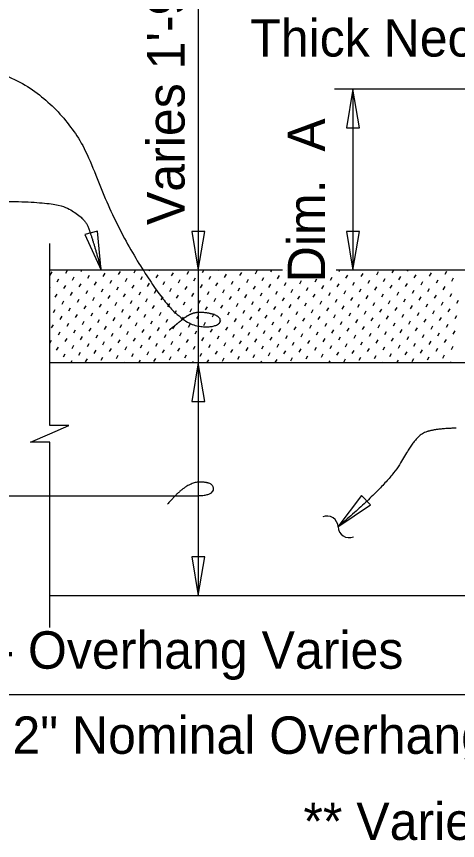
# Model space of a CAD drawing. Extents: x 21516.9 to 21586.2, y 56156.7 to 56193.6.
# Drawn here: x 21540.697 to 21543.073, y 56180.189 to 56184.631 of the extents above; entities that cross this region are included whole.
import ezdxf

# ---------------------------------------------------------------- set-up
doc = ezdxf.new("R2010")
doc.units = 0
for name, color, linetype in [('AdhocPoint_dp', 7, 'Continuous'), ('Patterning', 7, 'Continuous'), ('PlotBorder_dp', 7, 'Continuous'), ('SheetBorder_dp', 7, 'Continuous')]:
    doc.layers.add(name, color=color, linetype=linetype)

msp = doc.modelspace()

# ---------------------------------------------------------------- linework, layer by layer
at = {"layer": 'AdhocPoint_dp'}
for p, q in [((21544.8092, 56182.7637), (21540.8759, 56182.7637)), ((21540.8759, 56181.5106), (21544.9613, 56181.5106))]:
    msp.add_line(p, q, dxfattribs=at)
at = {"layer": 'Patterning'}
for p, q in [((21542.1295, 56183.2637), (21540.8759, 56183.2637)), ((21540.8787, 56183.2372), (21540.8884, 56183.254)), ((21540.9616, 56183.247), (21540.9713, 56183.2637)), ((21541.0446, 56183.2567), (21541.0486, 56183.2637)), ((21541.1641, 56183.2298), (21541.1738, 56183.2466)), ((21541.247, 56183.2395), (21541.2568, 56183.2563)), ((21541.33, 56183.2492), (21541.3383, 56183.2637)), ((21541.4129, 56183.259), (21541.4157, 56183.2637)), ((21541.5325, 56183.2321), (21541.5422, 56183.2489)), ((21541.6154, 56183.2418), (21541.6251, 56183.2586)), ((21541.6983, 56183.2515), (21541.7054, 56183.2637)), ((21541.7813, 56183.2613), (21541.7827, 56183.2637)), ((21541.9008, 56183.2344), (21541.9105, 56183.2512)), ((21541.9838, 56183.2441), (21541.9935, 56183.2609)), ((21542.0667, 56183.2538), (21542.0724, 56183.2637)), ((21542.1496, 56183.2635), (21542.1497, 56183.2637)), ((21542.1862, 56183.2269), (21542.196, 56183.2437)), ((21544.868, 56183.2637), (21542.4196, 56183.2637)), ((21542.4351, 56183.2561), (21542.4395, 56183.2637)), ((21542.5546, 56183.2292), (21542.5643, 56183.246)), ((21542.6375, 56183.2389), (21542.6473, 56183.2557)), ((21542.7205, 56183.2487), (21542.7292, 56183.2637)), ((21542.8034, 56183.2584), (21542.8065, 56183.2637)), ((21542.923, 56183.2315), (21542.9327, 56183.2483)), ((21543.0059, 56183.2412), (21543.0156, 56183.258)), ((21540.9153, 56183.2006), (21540.925, 56183.2174)), ((21540.9982, 56183.2104), (21541.008, 56183.2272)), ((21541.0812, 56183.2201), (21541.0909, 56183.2369)), ((21541.1178, 56183.1835), (21541.1275, 56183.2003)), ((21541.2007, 56183.1932), (21541.2104, 56183.21)), ((21541.2836, 56183.2029), (21541.2934, 56183.2197)), ((21541.3666, 56183.2126), (21541.3763, 56183.2294)), ((21541.4495, 56183.2224), (21541.4592, 56183.2392)), ((21541.4861, 56183.1858), (21541.4959, 56183.2025)), ((21541.5691, 56183.1955), (21541.5788, 56183.2123)), ((21541.652, 56183.2052), (21541.6617, 56183.222)), ((21541.7349, 56183.2149), (21541.7447, 56183.2317)), ((21541.8179, 56183.2246), (21541.8276, 56183.2414)), ((21541.8545, 56183.188), (21541.8642, 56183.2048)), ((21541.9374, 56183.1978), (21541.9472, 56183.2146)), ((21542.0204, 56183.2075), (21542.0301, 56183.2243)), ((21542.1033, 56183.2172), (21542.113, 56183.234)), ((21542.2228, 56183.1903), (21542.2326, 56183.2071)), ((21542.3058, 56183.2), (21542.3155, 56183.2168)), ((21542.3887, 56183.2098), (21542.3984, 56183.2266)), ((21542.4717, 56183.2195), (21542.4814, 56183.2363)), ((21542.5083, 56183.1829), (21542.518, 56183.1997)), ((21542.5912, 56183.1926), (21542.6009, 56183.2094)), ((21542.6741, 56183.2023), (21542.6839, 56183.2191)), ((21542.7571, 56183.2121), (21542.7668, 56183.2288)), ((21542.84, 56183.2218), (21542.8497, 56183.2386)), ((21542.8766, 56183.1852), (21542.8864, 56183.202)), ((21542.9596, 56183.1949), (21542.9693, 56183.2117)), ((21543.0425, 56183.2046), (21543.0522, 56183.2214)), ((21540.8759, 56183.1663), (21540.8787, 56183.1711)), ((21540.9519, 56183.164), (21540.9616, 56183.1808)), ((21541.0348, 56183.1737), (21541.0446, 56183.1905)), ((21541.1544, 56183.1469), (21541.1641, 56183.1637)), ((21541.2373, 56183.1566), (21541.247, 56183.1734)), ((21541.3203, 56183.1663), (21541.33, 56183.1831)), ((21541.4032, 56183.176), (21541.4129, 56183.1928)), ((21541.4398, 56183.1394), (21541.4495, 56183.1562)), ((21541.5227, 56183.1491), (21541.5325, 56183.1659)), ((21541.6057, 56183.1589), (21541.6154, 56183.1757)), ((21541.6886, 56183.1686), (21541.6983, 56183.1854)), ((21541.7716, 56183.1783), (21541.7813, 56183.1951)), ((21541.8082, 56183.1417), (21541.8179, 56183.1585)), ((21541.8911, 56183.1514), (21541.9008, 56183.1682)), ((21541.974, 56183.1612), (21541.9838, 56183.1779)), ((21542.057, 56183.1709), (21542.0667, 56183.1877)), ((21542.1399, 56183.1806), (21542.1496, 56183.1974)), ((21542.1765, 56183.144), (21542.1862, 56183.1608)), ((21542.2595, 56183.1537), (21542.2692, 56183.1705)), ((21542.3424, 56183.1634), (21542.3521, 56183.1802)), ((21542.4253, 56183.1732), (21542.4351, 56183.19)), ((21542.5449, 56183.1463), (21542.5546, 56183.1631)), ((21542.6278, 56183.156), (21542.6375, 56183.1728)), ((21542.7108, 56183.1657), (21542.7205, 56183.1825)), ((21542.7937, 56183.1754), (21542.8034, 56183.1922)), ((21542.8303, 56183.1388), (21542.84, 56183.1556)), ((21542.9132, 56183.1486), (21542.923, 56183.1654)), ((21542.9962, 56183.1583), (21543.0059, 56183.1751)), ((21540.9056, 56183.1177), (21540.9153, 56183.1345)), ((21540.9885, 56183.1274), (21540.9982, 56183.1442)), ((21541.0714, 56183.1371), (21541.0812, 56183.1539)), ((21541.1081, 56183.1005), (21541.1178, 56183.1173)), ((21541.191, 56183.1103), (21541.2007, 56183.1271)), ((21541.2739, 56183.12), (21541.2836, 56183.1368)), ((21541.3569, 56183.1297), (21541.3666, 56183.1465)), ((21541.3935, 56183.0931), (21541.4032, 56183.1099)), ((21541.4764, 56183.1028), (21541.4861, 56183.1196)), ((21541.5593, 56183.1125), (21541.5691, 56183.1293)), ((21541.6423, 56183.1223), (21541.652, 56183.1391)), ((21541.7252, 56183.132), (21541.7349, 56183.1488)), ((21541.7618, 56183.0954), (21541.7716, 56183.1122)), ((21541.8448, 56183.1051), (21541.8545, 56183.1219)), ((21541.9277, 56183.1148), (21541.9374, 56183.1316)), ((21542.0106, 56183.1245), (21542.0204, 56183.1413)), ((21542.0936, 56183.1343), (21542.1033, 56183.1511)), ((21542.1302, 56183.0977), (21542.1399, 56183.1145)), ((21542.2131, 56183.1074), (21542.2228, 56183.1242)), ((21542.2961, 56183.1171), (21542.3058, 56183.1339)), ((21542.379, 56183.1268), (21542.3887, 56183.1436)), ((21542.4619, 56183.1366), (21542.4717, 56183.1533)), ((21542.4985, 56183.0999), (21542.5083, 56183.1167)), ((21542.5815, 56183.1097), (21542.5912, 56183.1265)), ((21542.6644, 56183.1194), (21542.6741, 56183.1362)), ((21542.7474, 56183.1291), (21542.7571, 56183.1459)), ((21542.8669, 56183.1022), (21542.8766, 56183.119)), ((21542.9498, 56183.112), (21542.9596, 56183.1287)), ((21543.0328, 56183.1217), (21543.0425, 56183.1385)), ((21540.9422, 56183.0811), (21540.9519, 56183.0979)), ((21541.0251, 56183.0908), (21541.0348, 56183.1076)), ((21541.0617, 56183.0542), (21541.0714, 56183.071)), ((21541.1447, 56183.0639), (21541.1544, 56183.0807)), ((21541.2276, 56183.0736), (21541.2373, 56183.0904)), ((21541.3105, 56183.0834), (21541.3203, 56183.1002)), ((21541.4301, 56183.0565), (21541.4398, 56183.0733)), ((21541.513, 56183.0662), (21541.5227, 56183.083)), ((21541.596, 56183.0759), (21541.6057, 56183.0927)), ((21541.6789, 56183.0857), (21541.6886, 56183.1024)), ((21541.7155, 56183.049), (21541.7252, 56183.0658)), ((21541.7984, 56183.0588), (21541.8082, 56183.0756)), ((21541.8814, 56183.0685), (21541.8911, 56183.0853)), ((21541.9643, 56183.0782), (21541.974, 56183.095)), ((21542.0473, 56183.0879), (21542.057, 56183.1047)), ((21542.0839, 56183.0513), (21542.0936, 56183.0681)), ((21542.1668, 56183.0611), (21542.1765, 56183.0778)), ((21542.2497, 56183.0708), (21542.2595, 56183.0876)), ((21542.3327, 56183.0805), (21542.3424, 56183.0973)), ((21542.4156, 56183.0902), (21542.4253, 56183.107)), ((21542.4522, 56183.0536), (21542.4619, 56183.0704)), ((21542.5352, 56183.0633), (21542.5449, 56183.0801)), ((21542.6181, 56183.0731), (21542.6278, 56183.0899)), ((21542.701, 56183.0828), (21542.7108, 56183.0996)), ((21542.784, 56183.0925), (21542.7937, 56183.1093)), ((21542.8206, 56183.0559), (21542.8303, 56183.0727)), ((21542.9035, 56183.0656), (21542.9132, 56183.0824)), ((21542.9865, 56183.0753), (21542.9962, 56183.0921)), ((21543.0694, 56183.0851), (21543.0791, 56183.1019)), ((21540.8958, 56183.0348), (21540.9056, 56183.0516)), ((21540.9788, 56183.0445), (21540.9885, 56183.0613)), ((21541.0154, 56183.0079), (21541.0251, 56183.0247)), ((21541.0983, 56183.0176), (21541.1081, 56183.0344)), ((21541.1813, 56183.0273), (21541.191, 56183.0441)), ((21541.2642, 56183.037), (21541.2739, 56183.0538)), ((21541.3471, 56183.0468), (21541.3569, 56183.0636)), ((21541.3837, 56183.0102), (21541.3935, 56183.027)), ((21541.4667, 56183.0199), (21541.4764, 56183.0367)), ((21541.5496, 56183.0296), (21541.5593, 56183.0464)), ((21541.6326, 56183.0393), (21541.6423, 56183.0561)), ((21541.7521, 56183.0124), (21541.7618, 56183.0292)), ((21541.835, 56183.0222), (21541.8448, 56183.039)), ((21541.918, 56183.0319), (21541.9277, 56183.0487)), ((21542.0009, 56183.0416), (21542.0106, 56183.0584)), ((21542.0375, 56183.005), (21542.0473, 56183.0218)), ((21542.1205, 56183.0147), (21542.1302, 56183.0315)), ((21542.2034, 56183.0244), (21542.2131, 56183.0412)), ((21542.2863, 56183.0342), (21542.2961, 56183.051)), ((21542.3693, 56183.0439), (21542.379, 56183.0607)), ((21542.4059, 56183.0073), (21542.4156, 56183.0241)), ((21542.4888, 56183.017), (21542.4985, 56183.0338)), ((21542.5718, 56183.0267), (21542.5815, 56183.0435)), ((21542.6547, 56183.0365), (21542.6644, 56183.0532)), ((21542.7376, 56183.0462), (21542.7474, 56183.063)), ((21542.7742, 56183.0096), (21542.784, 56183.0264)), ((21542.8572, 56183.0193), (21542.8669, 56183.0361)), ((21542.9401, 56183.029), (21542.9498, 56183.0458)), ((21543.0231, 56183.0387), (21543.0328, 56183.0555)), ((21540.9325, 56182.9982), (21540.9422, 56183.0149)), ((21540.9691, 56182.9615), (21540.9788, 56182.9783)), ((21541.052, 56182.9713), (21541.0617, 56182.9881)), ((21541.1349, 56182.981), (21541.1447, 56182.9978)), ((21541.2179, 56182.9907), (21541.2276, 56183.0075)), ((21541.3008, 56183.0004), (21541.3105, 56183.0172)), ((21541.3374, 56182.9638), (21541.3471, 56182.9806)), ((21541.4204, 56182.9735), (21541.4301, 56182.9903)), ((21541.5033, 56182.9833), (21541.513, 56183.0001)), ((21541.5862, 56182.993), (21541.596, 56183.0098)), ((21541.6692, 56183.0027), (21541.6789, 56183.0195)), ((21541.7058, 56182.9661), (21541.7155, 56182.9829)), ((21541.7887, 56182.9758), (21541.7984, 56182.9926)), ((21541.8717, 56182.9856), (21541.8814, 56183.0023)), ((21541.9546, 56182.9953), (21541.9643, 56183.0121)), ((21542.0741, 56182.9684), (21542.0839, 56182.9852)), ((21542.1571, 56182.9781), (21542.1668, 56182.9949)), ((21542.24, 56182.9878), (21542.2497, 56183.0046)), ((21542.3229, 56182.9976), (21542.3327, 56183.0144)), ((21542.3596, 56182.961), (21542.3693, 56182.9777)), ((21542.4425, 56182.9707), (21542.4522, 56182.9875)), ((21542.5254, 56182.9804), (21542.5352, 56182.9972)), ((21542.6084, 56182.9901), (21542.6181, 56183.0069)), ((21542.6913, 56182.9998), (21542.701, 56183.0166)), ((21542.7279, 56182.9632), (21542.7376, 56182.98)), ((21542.8109, 56182.973), (21542.8206, 56182.9898)), ((21542.8938, 56182.9827), (21542.9035, 56182.9995)), ((21542.9767, 56182.9924), (21542.9865, 56183.0092)), ((21543.0597, 56183.0021), (21543.0694, 56183.0189)), ((21540.8861, 56182.9518), (21540.8958, 56182.9686)), ((21541.0057, 56182.9249), (21541.0154, 56182.9417)), ((21541.0886, 56182.9347), (21541.0983, 56182.9515)), ((21541.1715, 56182.9444), (21541.1813, 56182.9612)), ((21541.2545, 56182.9541), (21541.2642, 56182.9709)), ((21541.2911, 56182.9175), (21541.3008, 56182.9343)), ((21541.374, 56182.9272), (21541.3837, 56182.944)), ((21541.457, 56182.9369), (21541.4667, 56182.9537)), ((21541.5399, 56182.9467), (21541.5496, 56182.9635)), ((21541.6228, 56182.9564), (21541.6326, 56182.9732)), ((21541.6594, 56182.9198), (21541.6692, 56182.9366)), ((21541.7424, 56182.9295), (21541.7521, 56182.9463)), ((21541.8253, 56182.9392), (21541.835, 56182.956)), ((21541.9083, 56182.9489), (21541.918, 56182.9657)), ((21541.9912, 56182.9587), (21542.0009, 56182.9755)), ((21542.0278, 56182.9221), (21542.0375, 56182.9389)), ((21542.1107, 56182.9318), (21542.1205, 56182.9486)), ((21542.1937, 56182.9415), (21542.2034, 56182.9583)), ((21542.2766, 56182.9512), (21542.2863, 56182.968)), ((21542.3962, 56182.9243), (21542.4059, 56182.9411)), ((21542.4791, 56182.9341), (21542.4888, 56182.9509)), ((21542.562, 56182.9438), (21542.5718, 56182.9606)), ((21542.645, 56182.9535), (21542.6547, 56182.9703)), ((21542.6816, 56182.9169), (21542.6913, 56182.9337)), ((21542.7645, 56182.9266), (21542.7742, 56182.9434)), ((21542.8475, 56182.9364), (21542.8572, 56182.9531)), ((21542.9304, 56182.9461), (21542.9401, 56182.9629)), ((21543.0133, 56182.9558), (21543.0231, 56182.9726)), ((21543.0499, 56182.9192), (21543.0597, 56182.936)), ((21540.9227, 56182.9152), (21540.9325, 56182.932)), ((21540.9593, 56182.8786), (21540.9691, 56182.8954)), ((21541.0423, 56182.8883), (21541.052, 56182.9051)), ((21541.1252, 56182.8981), (21541.1349, 56182.9148)), ((21541.2082, 56182.9078), (21541.2179, 56182.9246)), ((21541.2448, 56182.8712), (21541.2545, 56182.888)), ((21541.3277, 56182.8809), (21541.3374, 56182.8977)), ((21541.4106, 56182.8906), (21541.4204, 56182.9074)), ((21541.4936, 56182.9003), (21541.5033, 56182.9171)), ((21541.5765, 56182.9101), (21541.5862, 56182.9269)), ((21541.6131, 56182.8734), (21541.6228, 56182.8902)), ((21541.6961, 56182.8832), (21541.7058, 56182.9)), ((21541.779, 56182.8929), (21541.7887, 56182.9097)), ((21541.8619, 56182.9026), (21541.8717, 56182.9194)), ((21541.9449, 56182.9123), (21541.9546, 56182.9291)), ((21541.9815, 56182.8757), (21541.9912, 56182.8925)), ((21542.0644, 56182.8855), (21542.0741, 56182.9022)), ((21542.1474, 56182.8952), (21542.1571, 56182.912)), ((21542.2303, 56182.9049), (21542.24, 56182.9217)), ((21542.3132, 56182.9146), (21542.3229, 56182.9314)), ((21542.3498, 56182.878), (21542.3596, 56182.8948)), ((21542.4328, 56182.8877), (21542.4425, 56182.9045)), ((21542.5157, 56182.8975), (21542.5254, 56182.9143)), ((21542.5986, 56182.9072), (21542.6084, 56182.924)), ((21542.7182, 56182.8803), (21542.7279, 56182.8971)), ((21542.8011, 56182.89), (21542.8109, 56182.9068)), ((21542.8841, 56182.8997), (21542.8938, 56182.9165)), ((21542.967, 56182.9095), (21542.9767, 56182.9263)), ((21543.0036, 56182.8729), (21543.0133, 56182.8897)), ((21540.8764, 56182.8689), (21540.8861, 56182.8857)), ((21540.913, 56182.8323), (21540.9227, 56182.8491)), ((21540.9959, 56182.842), (21541.0057, 56182.8588)), ((21541.0789, 56182.8517), (21541.0886, 56182.8685)), ((21541.1618, 56182.8614), (21541.1715, 56182.8782)), ((21541.2814, 56182.8346), (21541.2911, 56182.8514)), ((21541.3643, 56182.8443), (21541.374, 56182.8611)), ((21541.4472, 56182.854), (21541.457, 56182.8708)), ((21541.5302, 56182.8637), (21541.5399, 56182.8805)), ((21541.5668, 56182.8271), (21541.5765, 56182.8439)), ((21541.6497, 56182.8368), (21541.6594, 56182.8536)), ((21541.7327, 56182.8466), (21541.7424, 56182.8634)), ((21541.8156, 56182.8563), (21541.8253, 56182.8731)), ((21541.8985, 56182.866), (21541.9083, 56182.8828)), ((21541.9351, 56182.8294), (21541.9449, 56182.8462)), ((21542.0181, 56182.8391), (21542.0278, 56182.8559)), ((21542.101, 56182.8488), (21542.1107, 56182.8656)), ((21542.184, 56182.8586), (21542.1937, 56182.8754)), ((21542.2669, 56182.8683), (21542.2766, 56182.8851)), ((21542.3035, 56182.8317), (21542.3132, 56182.8485)), ((21542.3864, 56182.8414), (21542.3962, 56182.8582)), ((21542.4694, 56182.8511), (21542.4791, 56182.8679)), ((21542.5523, 56182.8609), (21542.562, 56182.8776)), ((21542.6353, 56182.8706), (21542.645, 56182.8874)), ((21542.6719, 56182.834), (21542.6816, 56182.8508)), ((21542.7548, 56182.8437), (21542.7645, 56182.8605)), ((21542.8377, 56182.8534), (21542.8475, 56182.8702)), ((21542.9207, 56182.8631), (21542.9304, 56182.8799)), ((21542.9573, 56182.8265), (21542.967, 56182.8433)), ((21543.0402, 56182.8363), (21543.0499, 56182.853)), ((21540.8759, 56182.8019), (21540.8764, 56182.8027)), ((21540.9496, 56182.7957), (21540.9593, 56182.8125)), ((21541.0326, 56182.8054), (21541.0423, 56182.8222)), ((21541.1155, 56182.8151), (21541.1252, 56182.8319)), ((21541.1984, 56182.8248), (21541.2082, 56182.8416)), ((21541.235, 56182.7882), (21541.2448, 56182.805)), ((21541.318, 56182.798), (21541.3277, 56182.8147)), ((21541.4009, 56182.8077), (21541.4106, 56182.8245)), ((21541.4838, 56182.8174), (21541.4936, 56182.8342)), ((21541.6034, 56182.7905), (21541.6131, 56182.8073)), ((21541.6863, 56182.8002), (21541.6961, 56182.817)), ((21541.7693, 56182.81), (21541.779, 56182.8268)), ((21541.8522, 56182.8197), (21541.8619, 56182.8365)), ((21541.8888, 56182.7831), (21541.8985, 56182.7999)), ((21541.9718, 56182.7928), (21541.9815, 56182.8096)), ((21542.0547, 56182.8025), (21542.0644, 56182.8193)), ((21542.1376, 56182.8122), (21542.1474, 56182.829)), ((21542.2206, 56182.822), (21542.2303, 56182.8388)), ((21542.2572, 56182.7854), (21542.2669, 56182.8022)), ((21542.3401, 56182.7951), (21542.3498, 56182.8119)), ((21542.423, 56182.8048), (21542.4328, 56182.8216)), ((21542.506, 56182.8145), (21542.5157, 56182.8313)), ((21542.5889, 56182.8242), (21542.5986, 56182.841)), ((21542.6255, 56182.7876), (21542.6353, 56182.8044)), ((21542.7085, 56182.7974), (21542.7182, 56182.8142)), ((21542.7914, 56182.8071), (21542.8011, 56182.8239)), ((21542.8743, 56182.8168), (21542.8841, 56182.8336)), ((21542.9939, 56182.7899), (21543.0036, 56182.8067)), ((21540.9116, 56182.7637), (21540.913, 56182.7661)), ((21540.9889, 56182.7637), (21540.9959, 56182.7759)), ((21541.0692, 56182.7688), (21541.0789, 56182.7856)), ((21541.1521, 56182.7785), (21541.1618, 56182.7953)), ((21541.2786, 56182.7637), (21541.2814, 56182.7684)), ((21541.3559, 56182.7637), (21541.3643, 56182.7781)), ((21541.4375, 56182.7711), (21541.4472, 56182.7879)), ((21541.5205, 56182.7808), (21541.5302, 56182.7976)), ((21541.6457, 56182.7637), (21541.6497, 56182.7707)), ((21541.723, 56182.7637), (21541.7327, 56182.7804)), ((21541.8059, 56182.7734), (21541.8156, 56182.7901)), ((21542.0127, 56182.7637), (21542.0181, 56182.773)), ((21542.0913, 56182.7659), (21542.101, 56182.7827)), ((21542.1742, 56182.7756), (21542.184, 56182.7924)), ((21542.3024, 56182.7637), (21542.3035, 56182.7655)), ((21542.3797, 56182.7637), (21542.3864, 56182.7753)), ((21542.4597, 56182.7682), (21542.4694, 56182.785)), ((21542.5426, 56182.7779), (21542.5523, 56182.7947)), ((21542.6695, 56182.7637), (21542.6719, 56182.7678)), ((21542.7468, 56182.7637), (21542.7548, 56182.7775)), ((21542.828, 56182.7705), (21542.8377, 56182.7873)), ((21542.911, 56182.7802), (21542.9207, 56182.797)), ((21543.0365, 56182.7637), (21543.0402, 56182.7701))]:
    msp.add_line(p, q, dxfattribs=at)
at = {"layer": 'PlotBorder_dp'}
for p, q in [((21541.6762, 56188.5971), (21541.6762, 56181.5106)), ((21544.9068, 56184.2384), (21542.4096, 56184.2384)), ((21542.5096, 56184.2384), (21542.5096, 56183.2637)), ((21545.8926, 56180.9739), (21538.0721, 56180.9739))]:
    msp.add_line(p, q, dxfattribs=at)
for points in [[(21542.5096, 56184.2383), (21542.4743, 56184.0301), (21542.5449, 56184.0301)], [(21541.1536, 56183.2637), (21541.1323, 56183.4739), (21541.0643, 56183.4551)], [(21541.6762, 56183.2637), (21541.7114, 56183.472), (21541.6409, 56183.472)], [(21542.5096, 56183.2637), (21542.5449, 56183.472), (21542.4743, 56183.472)], [(21541.6762, 56182.7637), (21541.6409, 56182.5555), (21541.7114, 56182.5555)], [(21542.4289, 56181.8803), (21542.6044, 56181.9979), (21542.5558, 56182.0491)], [(21541.6762, 56181.5106), (21541.7114, 56181.7189), (21541.6409, 56181.7189)]]:
    msp.add_lwpolyline(points, close=True, dxfattribs=at)
msp.add_lwpolyline([(21540.876, 56181.3378), (21540.876, 56182.3364), (21540.7727, 56182.3364), (21540.876, 56182.3814), (21540.9793, 56182.4264), (21540.876, 56182.4264), (21540.876, 56183.407)], dxfattribs=at)
for centre, start, end in [((21542.3699, 56181.8785), 1.3261, 113.0533), ((21542.4891, 56181.8812), 181.3261, 293.0533)]:
    msp.add_arc(centre, 0.0596, start, end, dxfattribs=at)
for points in [[(21540.1048, 56184.3923), (21540.5571, 56184.3958), (21541.0139, 56184.0712), (21541.218, 56183.5244), (21541.4787, 56183.1023), (21541.6204, 56182.9718), (21541.7253, 56182.9534), (21541.7948, 56182.9718), (21541.7948, 56183.013), (21541.7239, 56183.0356), (21541.6374, 56183.0356), (21541.5467, 56182.9619), (21541.5198, 56182.9406)], [(21540.2779, 56183.6305), (21540.8673, 56183.6475), (21541.0566, 56183.5558), (21541.1026, 56183.4489), (21541.1536, 56183.2637)], [(21543.0654, 56182.4119), (21542.9321, 56182.4084), (21542.8432, 56182.3606), (21542.703, 56182.1109), (21542.4289, 56181.8803)], [(21540.503, 56182.0479), (21540.7779, 56182.0479), (21541.1964, 56182.0479), (21541.566, 56182.0479), (21541.7584, 56182.0479), (21541.7584, 56182.1213), (21541.6088, 56182.1213), (21541.511, 56182.0021)]]:
    msp.add_open_spline(points, degree=2, dxfattribs=at)

# ---------------------------------------------------------------- texts
msp.add_text('Thick Neoprene Pad', height=0.2016, dxfattribs=at).set_placement((21541.956, 56184.4148))
at = {"layer": 'SheetBorder_dp'}
for s, p in [('Varies 1\'-9" to 2\'-0"', (21541.6023, 56183.5067)), ('Dim.  A', (21542.3596, 56183.1982))]:
    msp.add_text(s, height=0.2016, rotation=90, dxfattribs=at).set_placement(p)
for s, p in [('Schemes 3 & 4 - Overhang Varies ', (21538.6908, 56181.1153)), ('Schemes 5 & 6 - 2" Nominal Overhang', (21538.6072, 56180.6565)), ('** Varies 5', (21542.2429, 56180.1921))]:
    msp.add_text(s, height=0.2016, dxfattribs=at).set_placement(p)

doc.saveas('drawing.dxf')
